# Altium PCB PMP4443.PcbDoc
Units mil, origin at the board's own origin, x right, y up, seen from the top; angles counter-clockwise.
Board outline 2136.81 x 1725.39 mil, 2 copper layers (Top Layer, Bottom Layer), stack 62 mil thick; 21 components, 12 nets, 49 pads, 3 vias.
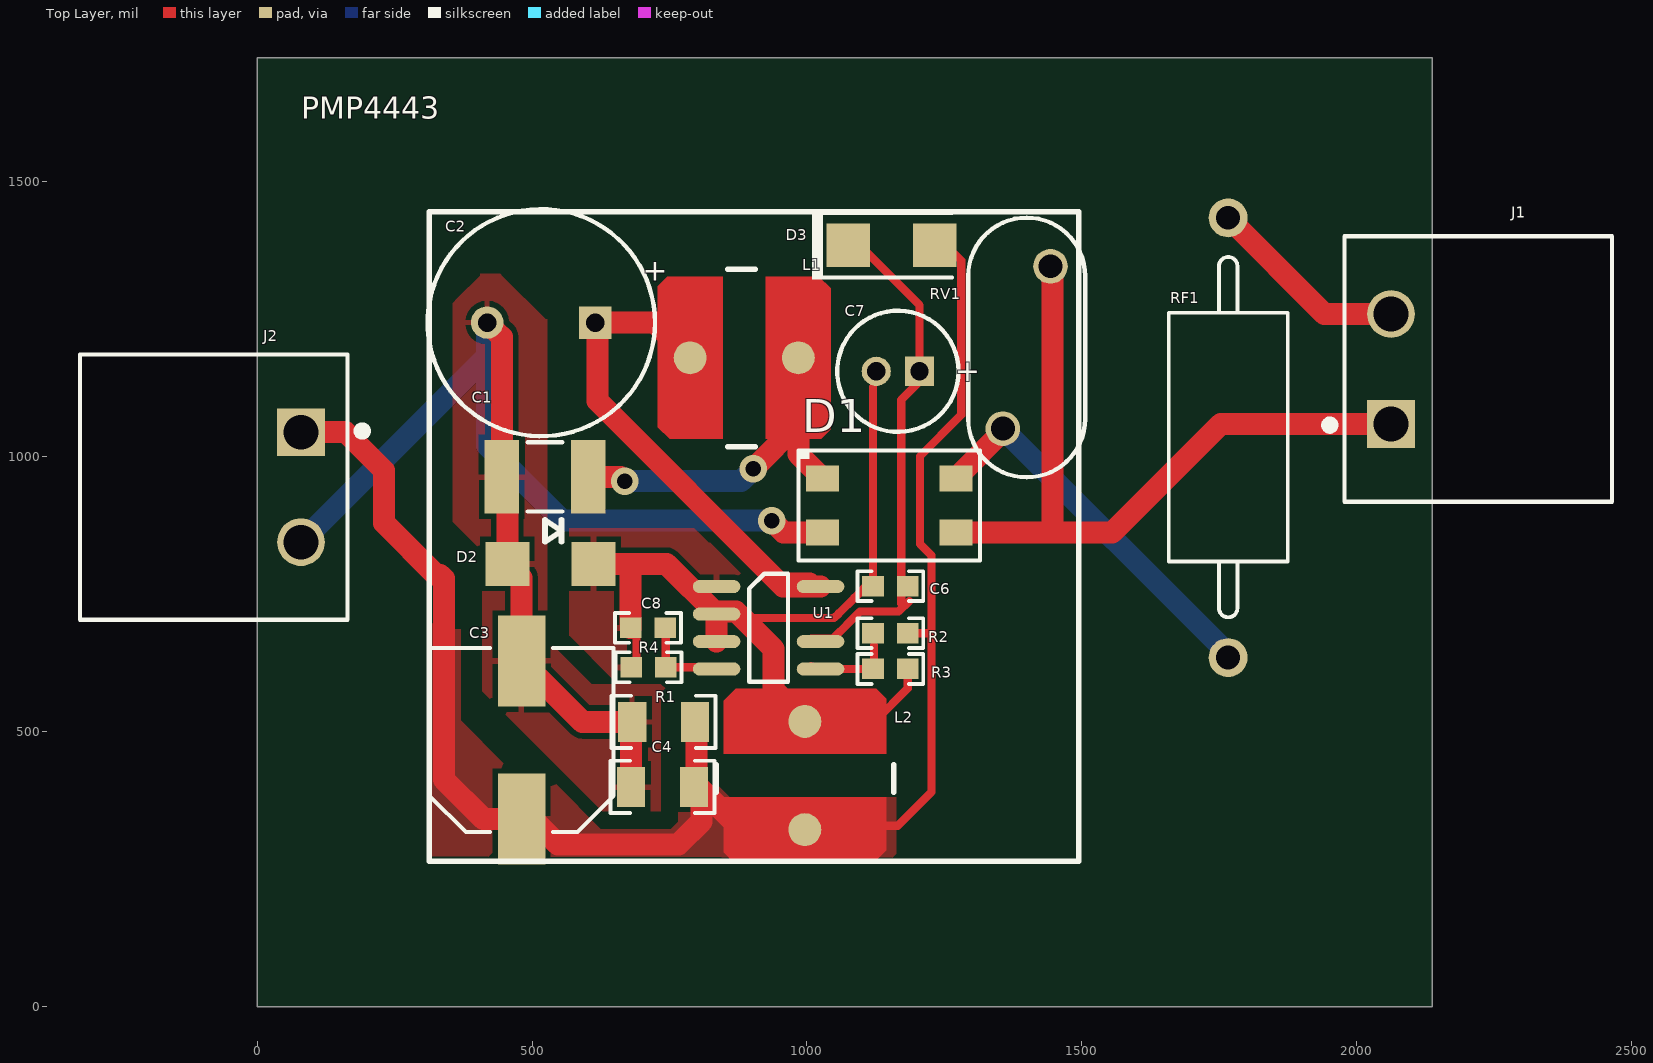
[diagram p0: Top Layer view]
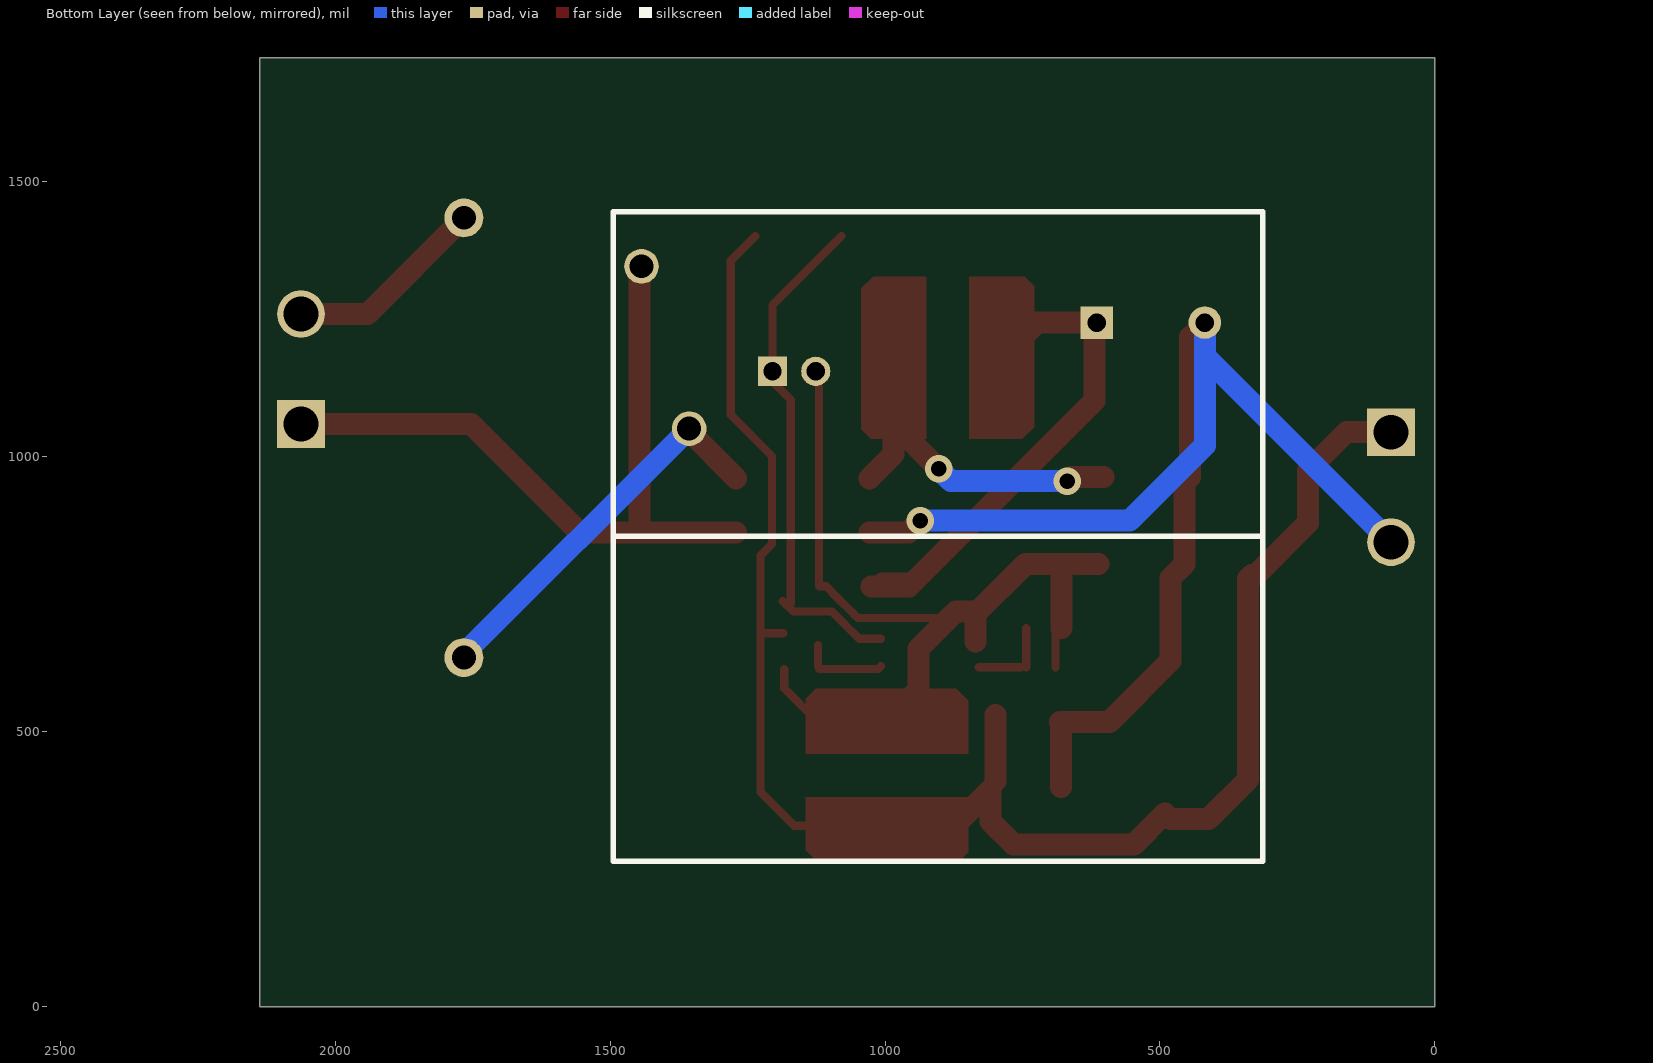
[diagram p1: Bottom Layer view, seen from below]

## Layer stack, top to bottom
Top Layer: signal copper 1.4
Dielectric: core 59.2, FR-4, Dk 4.8
Bottom Layer: signal copper 1.4

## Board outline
0,0 0,1725.39 2136.81,1725.39 2136.81,0

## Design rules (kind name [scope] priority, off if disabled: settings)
AcuteAngle [All] p1: minimum=4.50000000000000E+0001 checktracksonly=FALSE
AssemblyTestPointUsage [All] p1: valid=2
Clearance Clearance_1 [All] p1: gap=10
Clearance Clearance_BoardEdge_MountingHoles [OnCopper and InComponentClass('Mounting Holes') vs IsKeepOut] p2: gap=40
Clearance Clearance_BoardEdge_Poly [OnCopper and InPoly vs IsKeepOut] p3: gap=25
Clearance Clearance_BoardEdge [OnCopper and Not InComponentClass('Logo') and not InComponentClass('FiducialMark') and not InRegion(1000,500,4000,800) and Not IsKeepout vs IsKeepOut] p4: gap=75
Clearance Clearance_Poly [InPolygon] p5: gap=25
Clearance [All] p6: gap=7.87
ComponentClearance ComponentClearance_MountingHoles_FiducialMarks [InComponentClass('Mounting Holes') vs InComponentClass('FiducialMark')] p1: gap=0 collisioncheckmode=3 verticalgap=10 showdistances=FALSE
ComponentClearance ComponentClearance_Logo [InComponentClass('Logo')] p2: gap=0 collisioncheckmode=3 verticalgap=10 showdistances=FALSE
ComponentClearance ComponentClearance_ScrewToNut [(HasFootprint('NY PMS 440 0025 PH')) vs (HasFootprint('Keystone_1902C'))] p3: gap=0 collisioncheckmode=3 verticalgap=10 showdistances=FALSE
ComponentClearance ComponentClearance_MountingHoles [InComponentClass('Mounting Holes')] p4: gap=0 collisioncheckmode=3 verticalgap=100000 showdistances=FALSE
ComponentClearance ComponentClearance_SmallPassives [HasFootprint('0201*') or HasFootprint('0402*') or HasFootprint('0508') or HasFootprint('0603*') or HasFootprint('0612') or HasFootprint('0805*') or HasFootprint('0815*') or HasFootprint('0830*') or HasFootprint('1206*') or HasFootprint('1210*') or HasFootprint('1808*') or HasFootprint('1812*') or HasFootprint('1825*') or HasFootprint('2010*') or HasFootprint('2220*') or HasFootprint('2225*') or HasFootprint('2512*') or HasFootprint('2728*') or HasFootprint('3518*') vs HasFootprint('0201*') or HasFootprint('0402*') or HasFootprint('0508') or HasFootprint('0603*') or HasFootprint('0612') or HasFootprint('0805*') or HasFootprint('0815*') or HasFootprint('0830*') or HasFootprint('1206*') or HasFootprint('1210*') or HasFootprint('1808*') or HasFootprint('1812*') or HasFootprint('1825*') or HasFootprint('2010*') or HasFootprint('2220*') or HasFootprint('2225*') or HasFootprint('2512*') or HasFootprint('2728*') or HasFootprint('3518*')] p5: gap=0 collisioncheckmode=3 verticalgap=10 showdistances=FALSE
ComponentClearance ComponentClearance_THtoSMT [IsThruComponent vs IsSMTComponent] p6: gap=0 collisioncheckmode=3 verticalgap=30 showdistances=FALSE
ComponentClearance ComponentClearance_THtoTH [IsThruComponent vs IsThruComponent] p7: gap=0 collisioncheckmode=3 verticalgap=30 showdistances=FALSE
ComponentClearance [All] p8: gap=0 collisioncheckmode=3 verticalgap=10 showdistances=FALSE
ComponentClearance ComponentClearance_Shunt [InComponentClass('Header') vs InComponentClass('Shunt')] p9: gap=0 collisioncheckmode=3 verticalgap=0 showdistances=FALSE
DiffPairsRouting [All] p1: maxlimit=100 minlimit=10 mostfreqgap=10 maxuncoupledlength=1000
FabricationTestPointUsage TestPointUsage [All] p1: valid=2 allowmultiple=FALSE
FabricationTestpoint Testpoint [All] p1: side=3 testpointundercomponent=TRUE minsize=40 maxsize=100 preferedsize=60 minholesize=0 maxholesize=40 preferedholesize=32 testpointgrid=1 allowsidetop=TRUE allowsidebottom=TRUE usegrid=TRUE gridtolerance=0.01
FanoutControl Fanout_LCC [IsLCC] p1: bgadir=Out bgaviamode=Centered fanoutstyle=Auto fanoutdirection=Alternating viagrid=1 // Fanout_LCC (Default Rule)
FanoutControl Fanout_BGA [IsBGA] p2: bgadir=Out bgaviamode=Centered fanoutstyle=Auto fanoutdirection=Alternating viagrid=1 // Fanout_BGA (Default Rule)
FanoutControl Fanout_Default [All] p4: bgadir=Out bgaviamode=Centered fanoutstyle=Auto fanoutdirection=Alternating viagrid=1 // Fanout_Default (Default Rule)
FanoutControl Fanout_Small [(CompPinCount < 5)] p5: bgadir=Out bgaviamode=Centered fanoutstyle=Auto fanoutdirection=OutThenIn viagrid=1 // Fanout_Small (Default Rule)
HoleSize [All] p1: absolutevalues=TRUE maxlimit=251 minlimit=8 maxpercent=80.000 minpercent=20.000
MinimumAnnularRing MinimumAnnularRing_ThermalPadVias [IsVia and InAnyComponent] p1: minimumring=5.91
MinimumAnnularRing [All] p2: minimumring=9
MinimumSolderMaskSliver MinimumSolderMaskSliver_Logo [InComponentClass('Logo') vs InComponentClass('Logo')] p1: minsoldermaskwidth=0.7
MinimumSolderMaskSliver [All] p2: minsoldermaskwidth=3.94
PlaneConnect [All] p1: planeconnectstyle=Relief reliefexpansion=10 reliefentries=4 reliefconductorwidth=10 reliefairgap=10
PolygonConnect [All] p1: connectstyle=Relief reliefconductorwidth=10 reliefentries=4 polygonreliefangle="90 Angle" airgapwidth=10
RoomDefinition "V3-PMP4443-layout-Buck converter with  20Vout 2W" [InComponentClass('V3-PMP4443-layout-Buck converter with  20Vout 2W')] p1: confinementstyle=ConfineIn formatcopy=TRUE lockcomponents=FALSE outline -1076.06,-1819.28 923.94,-1819.28 923.94,-819.28 -1076.06,-819.28
RoutingVias ThermalPadVias [IsVia and InAnyComponent] p1: holewidth=7.87 width=19.68 viastyle="Through Hole" minholewidth=7.87 minwidth=19.68 maxholewidth=12.99 maxwidth=23.62
RoutingVias [All] p2: holewidth=16 width=34 viastyle="Through Hole" minholewidth=7.87 minwidth=26 maxholewidth=40 maxwidth=65
SMDToCorner [All] p1: distance=30000
SilkToSilkClearance [All] p1: silktosilkclearance=5
SilkscreenOverComponentPads [All] p1: minsilkscreentomaskgap=5
SolderMaskExpansion [All] p1: expansion=1.97
Width [All] p1: maxlimit=100 minlimit=6 preferedwidth=19.68 checkconnectedcopper=TRUE
14 further rules are at their usual default settings.

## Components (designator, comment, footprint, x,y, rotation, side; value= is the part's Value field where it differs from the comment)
C1 "VJ1812Y104KXEAT5Z" 1812 523.62,963.58 r180 top
C2 "UVC2G100MPD" VR_1000x1250 516.73,1244.09 r180 top (schematic designator C10)
C3 "EMVA500ADA101MHA0G" CAPSMT_62_HA0 480.94,484.72 r90 top (schematic designator C13)
C4 "12065C104JAT2A" 1206 737.2,399.61 r180 top (schematic designator C12)
C6 "06033D104KAT2A" 0603 1151.57,764.74 r180 top (schematic designator C7)
C7 "EEU-FM1E470" FM_500x1100 1165.35,1155.51 r180 top (schematic designator C8)
C8 "06033C101KAT2A" 0603 710.63,688.98 r180 top
D1 "RH06-T" MiniDIP 1149.61,911.42 r0 top (schematic designator D0)
D2 "US1G-E3/5AT" DO-214AC 533.46,805.12 r180 top
D3 "MURA160T3G" SMA 1153.54,1384.84 r0 top
J1 "20020110-H021A01LF" FCI_20020110-H021A01LF 2220.94,1159.72 r90 top (schematic designator J3)
J2 "20020110-H021A01LF" FCI_20020110-H021A01LF -79.06,944.72 r270 top
L1 "1mH" WE-PD2-L 885.83,1180.12 r180 top
L2 "220uH" WE-PD2-L 996.06,420.28 r270 top
R1 "RC1206FR-0720KL" 1206 739.17,517.72 r0 top (schematic designator R7)
R2 "RT0603DRE07336KL" 0603 1151.57,679.11 r0 top (schematic designator R4)
R3 "RT0603DRE0784K5L" 0603 1151.57,614.17 r180 top (schematic designator R6)
R4 "CRCW06031K30FKEA" 0603 711.61,617.13 r0 top
RF1 "PWR4522AS8R20JA" RES_PWR4522 1765.94,1034.72 r90 top (schematic designator RF2)
RV1 "S10K275E2" VAR_S10K275E2 1399.61,1198.82 r270 top
U1 "UCC28910D" D0007A_N 930.12,688.98 r0 top (schematic designator U2)

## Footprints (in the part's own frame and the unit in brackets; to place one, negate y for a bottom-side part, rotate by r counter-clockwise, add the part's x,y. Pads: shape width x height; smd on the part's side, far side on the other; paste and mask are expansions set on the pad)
0603 [mm] "0603 from SM-752 data"
  rect 1x0.95 smd: 1(-0.8,0) 2(0.8,0)
  silkscreen extent -1.52,-0.69 1.52,0.69, body extent -0.87,-0.47 0.87,0.47, height 0.85
1206 [mm] "1206 from SM-752 data"
  rect 1.3x1.85 smd: 1(-1.45,0) 2(1.45,0)
  silkscreen extent -2.4,-1.21 2.4,1.21, body extent -1.7,-0.9 1.7,0.9, height 1.35
1812 [mm]
  rect 1.6x3.4 smd: 1(-2,0) 2(2,0)
  silkscreen extent -0.8,-1.6 0.8,1.6, body extent -2.4,-1.7 2.4,1.7, height 1.35
CAPSMT_62_HA0 [mm] "8 x 10mm:  Chemi-Con HA0"
  rect 4.2x2.2 smd: 1(-3.65,0) 2(3.65,0)
  silkscreen extent -4.25,-4.25 4.25,4.25, body extent -4.26,-4.26 4.26,4.26, height 10.5
D0007A_N [mm] "SOIC, 7-Leads, Body 4.9x3.9mm, Pitch 1.27mm, IPC Medium Density"
  oval 2.2x0.6 smd: 1(-2.4,1.905) 2(-2.4,0.635) 3(-2.4,-0.635) 4(-2.4,-1.905) 5(2.4,-1.905) 6(2.4,-0.635) 8(2.4,1.905)
  silkscreen extent -0.9,-2.5 0.9,2.5, body extent -3,-2.5 3,2.5, height 1.54
DO-214AC [mil]
  rect 80x80 smd: 1(-78.5,0) 2(78.5,0)
  silkscreen extent -20,-80 10,-40
FCI_20020110-H021A01LF [mm] "FCI"
  rect 2.2x2.2 hole 1.6 paste+0 mask+0.05: 1(-2.54,4.03)
  round 2.2 hole 1.6 paste+0 mask+0.05: 2(2.54,4.03)
  silkscreen extent -6.13,-6.18 6.13,7.06, body extent -6.08,-6 6.08,6, height 8.67
FM_500x1100 [mm] "PANASONIC"
  rect 1.35x1.35 hole 0.838: 1(-1,0)
  round 1.35 hole 0.838: 2(1,0)
  silkscreen extent -2.8,-2.8 2.8,2.8, body extent -2.73,-2.75 2.75,2.75, height 12.51
MiniDIP [mm] "Land pattern created based on STEP model."
  rect 1.52x1.2 smd: 1(-3.075,1.25) 2(-3.075,-1.25) 3(3.075,-1.25) 4(3.075,1.25)
  silkscreen extent -4.19,-2.54 4.19,2.54, body extent -3.5,-2.45 3.5,2.45, height 2.75
RES_PWR4522 [mm] "Bourns fusible resistor"
  round 1.8 hole 1.1: 1(-10.16,0) 2(10.16,0)
  silkscreen extent -8.3,-2.76 8.35,2.74, body extent -10.58,-2.74 10.58,2.74, height 5.49
SMA [mm] "Molded Diode, 2-Leads, Body 4.3x2.6mm, IPC Medium Density, based on OnSemi component dimensions and land pattern"
  rect 2x2 smd: 1(-2,0) 2(2,0)
  silkscreen extent -3.66,-1.57 2.79,1.57, body extent -2.6,-1.3 2.6,1.3, height 2.42
VAR_S10K275E2 [mm] "EPCOS"
  round 1.6 hole 1.1: 1(-3.75,1.1) 2(3.75,-1.1)
  silkscreen extent -6,-2.7 6,2.7, body extent -5.98,-2.7 5.98,2.7, height 14.99
VR_1000x1250 [mm] "Nichicon"
  rect 1.5x1.5 hole 0.85: 1(-2.5,0)
  round 1.5 hole 0.85: 2(2.5,0)
  silkscreen extent -5.25,-5.25 5.25,5.25, body extent -5.21,-5.24 5.24,5.24, height 14.01
WE-PD2-L [mil] "WE, Inductor"
  round 60 smd: 1(-98.43,0) 2(98.43,0)
  Top Layer region: 39.37,147.64 39.37,-147.64 139.76,-147.64 157.48,-129.92 157.48,125.98 135.83,147.64
  Top Layer region: -39.37,-147.64 -39.37,147.64 -139.76,147.64 -157.48,129.92 -157.48,-125.98 -135.83,-147.64
  silkscreen extent -20,-161 30,161, body extent -157,-144 159,144, height 217

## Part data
C1: "CAP, CERM, 0.1uF, 500V, +/-10%, X7R, 1812"
C2: library part UVC2G8R2MPD, "CAP, AL, 10uF, 400V, +/-20%, TH"
C3: "CAP, AL, 100uF, 50V, +/-20%,  ohm, SMD"
C4: "CAP, CERM, 0.1uF, 50V, +/-5%, X7R, 1206"
C6: "CAP, CERM, 0.1uF, 25V, +/-10%, X5R, 0603"
C7: "CAP, AL, 47uF, 25V, +/-20%, 0.3 ohm, TH"
C8: "CAP, CERM, 100pF, 25V, +/-10%, X7R, 0603"
D1: "Diode, Switching-Bridge, 600V, 0.5A, MiniDIP"
D2: library part D_SCHOT_SS_SERIES, "Diode, Schottky, xxV, 1A"
D3: "Diode, Ultrafast, 600V, 1A, SMA"
J1 J2: "Terminal Block, 2x1, 5.08mm, TH"
L1: library part 76877530, "Inductor, Unshielded Drum Core, Metal Composite, 1mH, 0.3A, 2.78 ohm, SMD"
L2: library part 744775247, "Inductor, Unshielded Drum Core, Metal Composite, 470uH, 0.36A, 1.37 ohm, SMD"
R1: "RES, 20.0k ohm, 1%, 0.25W, 1206"
R2: "RES, 336k ohm, 0.5%, 0.1W, 0603"
R3: "RES, 84.5k ohm, 0.5%, 0.1W, 0603"
R4: "RES, 1.30k ohm, 1%, 0.1W, 0603"
RF1: "RES, 8.2 ohm, 5%, 3W, Fusible, TH"
RV1: "Varistor 275V RMS 10MM Radial, TH"
U1: "LOW STAND-BY POWER, CV / CC PWM HV SWITCHER WITH PRIMARY SIDE REGULATION, D0007A"

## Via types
v1: diameter 50, hole 28, Top Layer to Bottom Layer, 3 vias

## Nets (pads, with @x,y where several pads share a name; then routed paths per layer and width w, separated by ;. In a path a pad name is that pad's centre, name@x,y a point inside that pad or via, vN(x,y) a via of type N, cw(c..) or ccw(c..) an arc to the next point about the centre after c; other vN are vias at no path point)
GND0: C1.2 C2.2 C3.2 C4.2 D1.2 D2.2 J2.2 R1.1 | length 2383.1
  Top Layer w40: C2.2 444.88,1217.52 C1.2 454.96,953.5 D2.2 480.94,779.14 C3.2 591.65,517.72 R1.1 ; C4.2 R1.1@680.12,515.75 ; v1(936.02,883.86) 957.68,862.2 D1.2
  Bottom Layer w40: J2.2 418.31,1183.43 ; C2.2 418.31,1183.43 ; v1(936.02,883.86) 555.12,883.86 418.31,1020.67 418.31,1183.43
NetC1_1: C1.1 D1.1 L1.1 | length 666.2
  Top Layer w40: C1.1 660.43,963.58 v1(668.31,955.71) ; v1(902.56,978.35) 984.25,1060.04 ; L1.1 984.25,1060.04 ; D1.1 984.25,1004.92 984.25,1060.04
  Bottom Layer w40: v1(668.31,955.71) 879.92,955.71 v1(902.56,978.35)
NetC2_1: C2.1 L1.2 U1.8 | length 942.4
  Top Layer w40: L1.2 723.43,1244.09 C2.1 619.37,1239.88 619.37,1101.3 950.69,769.98 ; U1.8@1004.82,769.98 950.69,769.98 ; U1.8 956.69,763.98 950.69,769.98
NetC3_1: C3.1 C4.1 D3.2 J2.1 L2.2 R1.2 R2.2 | length 3086.2
  Top Layer w15: L2.2 1016.5,321.85 1023.39,328.74 1164.96,328.74 1226.38,390.16 1226.38,679.13 ; R2.2@1185.04,679.13 1226.38,679.13 ; D3.2@1235.98,1401.57 1280.51,1357.04 1280.51,1075.79 1205.71,1000.98 1205.71,841.54 1226.38,820.87 1226.38,679.13
  Top Layer w40: J2.1 160.94,1044.72 230.94,974.72 230.94,879.46 325.36,785.04 332.87,785.04 339.57,778.35 339.57,413.19 411.73,341.02 C3.1 ; C3.1@490.94,351.02 547.24,294.72 765.94,294.72 808.03,336.81 808.03,394.65 881.38,321.3 995.51,321.3 L2.2 ; C4.1@799.33,409.96 R1.2@799.33,529.96
NetC6_1: C6.1 C7.1 D3.1 U1.6 | length 941.3
  Top Layer w15: U1.6@1007.87,668.9 1046.73,668.9 1059.52,681.69 1082.89,705.02 ; D3.1@1078.98,1401.57 1204.72,1275.83 C7.1 1204.72,1136.81 1171.26,1103.35 1171.26,733.01 ; 1082.89,705.06 1096.33,718.5 1166.6,718.5 1186.02,737.93
NetC6_2: C6.2 C7.2 C8.2 D2.1 L2.1 R3.1 R4.1 U1.1 U1.2 U1.3 | length 1799.9
  Top Layer w15: R4.1@689.96,617.13 C8.2@689.96,702.01 ; 882.87,706.69 1049.21,706.69 1057.89,715.37 ; 973.43,546.26 998.03,521.65 1125.98,521.65 1183.07,578.74 R3.1 ; L2.1 L2.1@1014.76,537.4 ; 1057.89,715.42 1085.98,743.5 ; 1086.02,743.5 1107.26,764.74 C6.2 1120.08,1126.85
  Top Layer w40: C8.2 679.13,804.13 678.15,805.12 D2.1 744.49,805.12 U1.2 ; U1.3 U1.2 ; L2.1 938.98,575.79 938.98,650.59 882.87,706.69 870.67,718.9 835.63,718.9 U1.2
NetC8_1: C8.1 R4.2 U1.4 | length 147.8
  Top Layer w15: R4.2 C8.1@743.11,687.99 ; R4.2@752.95,617.13 U1.4@829.92,617.13
NetD0_3: D1.3 J1.1 RV1.1 | length 1359.3
  Top Layer w40: D1.3 1446.85,862.2 ; RV1.1 1446.85,1342.52 1446.85,862.2 ; J1.1 1752.64,1059.72 1555.12,862.2 1446.85,862.2
NetD0_4: D1.4 RF1.1 RV1.2 | length 712.2
  Top Layer w40: D1.4 1356.3,1046.26 RV1.2
  Bottom Layer w40: RV1.2 1765.94,641.54 RF1.1
NetD1_2: 
NetJ1_2: J1.2 RF1.2 | length 368.8
  Top Layer w40: RF1.2 1940.94,1259.72 J1.2
NetR2_1: R2.1 R3.2 U1.5 | length 151.8
  Top Layer w15: U1.5@1007.87,618.9 1012.6,614.17 R3.2 ; R3.2@1122.05,619.88 1122.05,657.48

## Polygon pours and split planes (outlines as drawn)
GND0 on Top Layer "Top Layer-No Net 4" (solid, pour order 19): 734.25,355.32 734.25,570.87 742.13,578.74 734.25,586.61 617.13,586.61 608.27,586.61 527.56,667.32 527.56,1250 524.61,1250 446.85,1327.76 441.93,1332.68 405.51,1332.68 405.51,1329.72 364.17,1288.39 355.32,1279.53 355.32,932.09 355.32,881.92 402.17,835.06 409.45,827.79 409.45,590.55 409.45,573.82 627.95,355.32
NetC6_2 on Top Layer "Top Layer-No Net 2" (solid, pour order 17): 660.43,560.04 660.43,581.69 569.88,672.24 567.91,674.21 567.91,870.08 795.28,870.08 876.97,788.39 962.6,702.76 962.6,566.93 912.4,566.93 900.59,578.74 898.62,580.71 898.62,648.62 812.01,648.62 799.21,661.42 795.28,665.35 795.28,709.65 795.28,716.54 774.61,737.2 771.65,734.25 691.93,734.25 691.93,561.02 688.98,558.07
NetC6_2 on Top Layer "Top Layer-No Net 3" (solid, remove dead copper, pour order 15): 568.9,845.47 568.9,683.98 568.9,679.13 639.76,608.27 641.73,606.3 698.82,606.3 698.82,723.43 709.65,712.6 799.21,712.6 799.21,653.54 809.06,643.7 925.2,643.7 925.2,728.35 932.09,735.24 823.82,843.5 568.9,843.5
NetC3_1 on Top Layer "Top Layer-No Net 1" (solid, remove dead copper, pour order 10): 1162.4,270.67 1162.4,379.17 1163.58,380.35 862.99,380.35 859.8,380.35 814.96,425.2 813.98,424.21 765.75,424.21 765.75,336.61 751.97,322.83 642.72,322.83 625,322.83 524.61,423.23 520.67,427.17 463.58,427.17 371.06,519.68 370.08,520.67 370.08,686.02 339.96,686.02 316.64,709.35 316.64,273.07

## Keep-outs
Keep-Out Layer:
  lines w10: 4565.94,-290.28 ccw(c4565.94,-285.28) 4570.95,-285.28 ; 4565.94,-290.28 ccw(c4565.94,-285.28) 4570.95,-285.28 ; 4565.94,-290.28 ccw(c4565.94,-285.28) 4570.95,-285.28 ; 4565.94,-290.28 ccw(c4565.94,-285.28) 4570.95,-285.28 ; 4565.94,-290.28 ccw(c4565.94,-285.28) 4570.95,-285.28 ; 4565.94,-290.28 ccw(c4565.94,-285.28) 4570.95,-285.28 ; 4565.94,3169.73 cw(c4565.94,3164.72) 4570.95,3164.72 ; 4565.94,3169.73 cw(c4565.94,3164.72) 4570.95,3164.72 ; 4565.94,3169.73 cw(c4565.94,3164.72) 4570.95,3164.72 ; 4565.94,3169.73 cw(c4565.94,3164.72) 4570.95,3164.72 ; 4565.94,3169.73 cw(c4565.94,3164.72) 4570.95,3164.72 ; 4565.94,3169.73 cw(c4565.94,3164.72) 4570.95,3164.72
  text ".Layer_Name" at 192.94,-1143.77 h60

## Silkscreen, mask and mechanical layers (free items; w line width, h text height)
Top Overlay:
  lines w10: 313.35,264.76 313.35,1445.87 1494.45,1445.87 1494.45,1052.68 1494.45,264.76 313.35,264.76
  text "PMP4443" at 79.72,1615.16 h40
Bottom Overlay:
  lines w10: 313.35,855.24 1494.45,855.24 ; 313.35,264.72 313.35,1445.63 1494.45,1445.63 1494.45,264.72 313.35,264.72
Drill Guide:
  text ".Layer_Name" at 192.94,-1143.77 h60
M1 Board Outline:
  lines w10: 0,0 2136.81,0 2136.81,1725.39 0,1725.39 0,0
  lines w47.24: 0,0 0,1725.39 2136.81,1725.39 2136.81,0 0,0
  text ".Layer_Name" at 192.94,-1143.77 h60
M2 Board Dimensions:
  text ".Layer_Name" at 192.94,-1143.77 h60
M3 3D STEP Top:
  text ".Layer_Name" at 192.94,-1143.77 h60
M4 3D STEP Bottom:
  text ".Layer_Name" at 192.94,-1143.77 h60
M5 Assembly Top:
  lines w10: -676.06,-1215.44 5923.94,-1215.44 ; -676.06,-1012.11 5925.94,-1012.11 ; -676.06,-808.78 -676.06,-1418.78 3328.94,-1418.78 5925.94,-1418.78 5925.94,-808.78 -675.56,-808.78 -675.56,-1418.78 899.94,-1418.78 ; 1788.94,-1418.78 1788.94,-808.78 ; 3055.94,-1012.11 3055.94,-808.78 ; 3895.94,-1012.11 3895.94,-808.78 ; 4517.94,-1425.28 4517.94,-1222.44
  text "COMPONENTS MARKED 'DNP' SHOULD NOT BE POPULATED." at 769.44,-603.78 h60
  text "ASSEMBLY VARIANT:" at 768.94,-719.28 h60
  text ".VariantName" at 1804.94,-719.28 h60
  text "PCB VIEWED FROM TOP SIDE" at -612.56,-940.94 h60
  text "BOARD #:" at 1863.94,-940.94 h60
  text ".PRJ_Number" at 2409.44,-940.94 h60
  text "REV:" at 3253.94,-940.94 h60
  text ".PCB_Rev" at 3545.44,-940.94 h60
  text "SVN REV:" at 4091.94,-940.94 h60
  text ".VersionControl_RevNumber" at 4597.94,-940.94 h60
  text "IGNORE ->" at -612.56,-1143.77 h60
  text "PLOT NAME =" at -612.56,-1349.61 h60
  text ".plot_File_Name" at 192.94,-1349.61 h60
  text "GENERATED    :" at 1865.94,-1349.61 h60
  text ".Print_Date" at 2735.44,-1349.61 h60
  text ".Print_Time" at 3464.44,-1349.61 h60
  text "TEXAS INSTRUMENTS" at 4728.94,-1349.61 h60
M6 Assembly Bottom:
  lines w10: -676.56,-1012.61 5925.44,-1012.61 ; -674.56,-1215.94 5925.44,-1215.94 ; 731.44,-1425.78 731.44,-1222.94 ; 1353.44,-1012.61 1353.44,-809.28 ; 2193.44,-1012.61 2193.44,-809.28 ; 3460.44,-1419.28 3460.44,-809.28 ; 4349.44,-1419.28 5924.94,-1419.28 5924.94,-809.28 -676.56,-809.28 -676.56,-1419.28 1920.44,-1419.28 5925.44,-1419.28 5925.44,-809.28
  text "COMPONENTS MARKED 'DNP' SHOULD NOT BE POPULATED." at 5717.94,-603.28 h60
  text ".VariantName" at 4673.94,-719.28 h60
  text "ASSEMBLY VARIANT:" at 5712.94,-719.28 h60
  text ".VersionControl_RevNumber" at 651.44,-941.44 h60
  text "SVN REV:" at 1157.44,-941.44 h60
  text ".PCB_Rev" at 1703.94,-941.44 h60
  text "REV:" at 1995.44,-941.44 h60
  text ".PRJ_Number" at 2839.94,-941.44 h60
  text "BOARD #:" at 3385.44,-941.44 h60
  text "PCB VIEWED FROM BOTTOM SIDE" at 5861.94,-941.44 h60
  text "IGNORE ->" at 2163.8,-1143.77 h60
  text "TEXAS INSTRUMENTS" at 520.44,-1350.11 h60
  text ".Print_Time" at 1784.94,-1350.11 h60
  text ".Print_Date" at 2513.94,-1350.11 h60
  text "GENERATED    :" at 3383.44,-1350.11 h60
  text ".plot_File_Name" at 5056.44,-1350.11 h60
  text "PLOT NAME =" at 5861.94,-1350.11 h60
M9 Title Sheet:
  drawing of 57 lines, arcs and shapes, not listed
  text "1" at 355.78,7751.22 h70
  text "2" at 2851.44,7751.22 h70
  text "3" at 5340.79,7751.22 h70
  text "4" at 7847.46,7751.22 h70
  text "5" at 10346.44,7751.22 h70
  text "6" at 12851.44,7751.22 h70
  text "A" at -800.56,6608.22 h70
  text "A" at 13999.44,6608.22 h70
  text "B" at -800.56,4228.22 h70
  text "B" at 13999.44,4228.22 h70
  text "C" at -800.56,1853.22 h70
  text "C" at 13999.44,1853.22 h70
  text "PROJECT TITLE:" at 10959.44,-7.78 h45
  text ".PRJ_Title" at 11009.44,-141.1 h70
  text "DESIGNED FOR:" at 10959.44,-308.78 h45
  text ".PRJ_Customer" at 11009.44,-448.78 h70
  text "D" at -800.56,-516.78 h70
  text "D" at 13999.44,-516.78 h70
  text "FILE NAME:" at 10959.44,-608.78 h45
  text ".PCB_File_Name_No_Path" at 11009.44,-728.78 h70
  text "Texas Instruments (TI) and/or its licensors do not warrant the accuracy or completeness of this specification" at 5989.94,-890.61 h45
  text "ENGINEER:" at 10959.44,-898.78 h45
  text "LAYOUT BY:" at 12464.44,-898.78 h45
  text "or any information contained therein. TI and/or its licensors do not warrant that this design will meet" at 5944.96,-1003.28 h45
  text ".PRJ_Engineer" at 11009.44,-1053.77 h70
  text ".PCB_Layout" at 12514.94,-1053.77 h70
  text "the specifications, will be suitable for your application or fit for any particular purpose, or will operate in" at 5944.96,-1115.94 h45
  text ".Layer_Name" at 192.94,-1143.77 h60
  text "ALTIUM DESIGNER VERSION:" at 12464.44,-1208.78 h45
  text "an implementation. TI and/or its licensors do not warrant that the design is production worthy. You should" at 5944.96,-1228.61 h45
  text "completely validate and test your design implementation to confirm the system functionality for your application." at 5989.94,-1341.28 h45
  text ".print_Scale" at 11009.44,-1342.1 h70
  text ".Application_BuildNumber" at 12514.94,-1342.1 h70
  text "1" at 355.78,-1548.78 h70
  text "2" at 2851.44,-1548.78 h70
  text "3" at 5340.79,-1548.78 h70
  text "4" at 7847.46,-1548.78 h70
  text "5" at 10346.44,-1548.78 h70
  text "6" at 12851.44,-1548.78 h70
M10 Fab Notes:
  drawing of 185 lines, arcs and shapes, not listed
  text "DESIGN INFORMATION" at 11996.96,5624.72 h60
  text "MIN. TRACK WIDTH:" at 11352.4,5444.72 h60
  text "15" at 12448.65,5444.73 h60
  text "MIL" at 12603.4,5444.72 h60
  text "MIN. CLEARANCE:" at 11352.4,5312.72 h60
  text "0.2" at 12388.65,5312.73 h60
  text "mm" at 12603.4,5312.72 h60
  text "MIN. VIA PAD SIZE:" at 11352.4,5180.72 h60
  text "20" at 12418.66,5180.73 h60
  text "MIL" at 12603.4,5180.72 h60
  text "0.05mm (2MIL)" at 12047.4,5039.01 h60
  text "MINIMUM ANNULAR RING" at 11023.17,5034.73 h60
  text "EXTERNAL" at 12755.4,5034.73 h60
  text "PER" at 11223.17,4916.73 h60
  text "IPC-D-275 CLASS 2 LEVEL C" at 11443.17,4916.72 h60
  text "MIL, HOLES" at 12931.4,4804.44 h60
  text "+/-" at 12538.94,4803.73 h60
  text "+/-" at 13392.94,4803.73 h60
  text "REGISTRATION TOLERANCES:" at 11023.17,4798.72 h60
  text "METAL" at 12222.94,4798.72 h60
  text "5" at 12799.15,4798.73 h60
  text "3" at 13632.15,4798.73 h60
  text "MIL" at 13748.4,4798.72 h60
  text "MATERIAL:" at 10948.4,4589.27 h60
  text "FR-4 High Tg" at 11934.85,4448.93 h60
  text "FR-408" at 11369.41,4440.36 h60
  text "X" at 11781.4,4440.36 h60
  text "OTHER" at 12857.4,4440.36 h60
  text "62 MIL (1.6mm) +/-10%" at 11689.51,4277.65 h60
  text "THICKNESS:" at 11023.17,4273.36 h60
  text "X" at 11561.34,4273.36 h60
  text "OTHER" at 12974.4,4273.36 h60
  text "TOLERANCE:" at 11023.17,4115.36 h60
  text "X" at 11862.48,4115.36 h60
  text "ANSI IPC-6012 TYPE 3 CLASS 2" at 12049.42,4115.36 h60
  text "OTHER +/-" at 12049.4,3959.36 h60
  text "BOW & TWIST:" at 11023.17,3802.36 h60
  text "X" at 11862.48,3802.36 h60
  text "ANSI IPC-6012 TYPE 3 CLASS 2" at 12049.42,3802.36 h60
  text "OTHER +/-" at 12049.4,3643.86 h60
  text "DRILLING:" at 10948.4,3505.36 h60
  text "REFERENCE:" at 11023.17,3388.36 h60
  text "X" at 11671.4,3388.36 h60
  text "AS SHOWN" at 11858.4,3388.36 h60
  text "X" at 12572.4,3388.36 h60
  text "NC_DRILL FILES" at 12709.4,3388.36 h60
  text "PTH MIN COPPER THICKNESS:" at 11023.17,3230.36 h60
  text "X" at 12373.4,3230.36 h60
  text "1MIL" at 12510.4,3230.36 h60
  text "OTHER" at 13007.4,3230.36 h60
  text "BOARD FINISH:" at 10948.4,3071.36 h60
  text "SILKSCREEN:" at 11103.63,2953.36 h60
  text "X" at 12052.4,2953.36 h60
  text "TOP" at 12178.4,2953.36 h60
  text "X" at 12562.4,2953.36 h60
  text "BOTTOM" at 12689.4,2953.36 h60
  text "SILKSCREEN COLOR:" at 11103.63,2786.36 h60
  text "X" at 12051.36,2786.36 h60
  text "WHITE" at 12178.4,2786.36 h60
  text "OTHER" at 12689.4,2786.36 h60
  text "SOLDER RESIST COLOR:" at 11103.63,2616.36 h60
  text "X" at 11671.37,2457.17 h60
  text "GREEN" at 11798.4,2457.17 h60
  text "BLUE" at 12389.4,2457.17 h60
  text "OTHER" at 12927.4,2457.17 h60
  text "IMMERSION GOLD (ENIG)" at 12009.4,2268.65 h60
  text "ENEPIG" at 13346.94,2265.36 h60
  text "SURFACE FINISH:" at 10948.4,2264.36 h60
  text "X" at 11822.46,2264.36 h60
  text "IMM. TIN/SILVER OR EQUIV" at 11277.94,2107.36 h60
  text "OTHER" at 12709.4,2107.36 h60
  text "ARRAY/PANEL:" at 10948.4,1928.36 h60
  text "CUT AND TRIM PER MECH LAYER 1" at 12009.41,1924.08 h60
  text "N.C. ROUTE" at 12009.4,1772.36 h60
  text "X" at 12688.4,1772.36 h60
  text "V. SCORE" at 12875.4,1772.36 h60
  text "CERTIFICATION:" at 10948.4,1635.36 h60
  text "MATERIALS AND WORKMANSHIP FOR ALL PCBS" at 11673.4,1635.36 h60
  text "TO MEET OR EXCEED THE REQUIREMENTS OF:" at 11673.4,1537.36 h60
  text "X" at 11299.91,1400.86 h60
  text "ANSI IPC-A-600F CLASS ->" at 11438.91,1400.86 h60
  text "X" at 13077.96,1400.86 h60
  text "2" at 13196.91,1400.86 h60
  text "1" at 12881.91,1399.36 h60
  text "3" at 13550.91,1399.36 h60
  text "X" at 11301.96,1241.36 h60
  text "UL 94V-0" at 11438.91,1241.36 h60
  text "X" at 12113.96,1241.36 h60
  text "RoHS" at 12250.91,1241.36 h60
  text "OTHER" at 12895.31,1241.36 h60
  text "PER ORDER" at 13292.37,1241.36 h60
  text "ADDITIONAL REQUIREMENTS:" at 10948.4,1100.36 h60
  text "MICROSECTION:" at 11023.17,985.36 h60
  text "YES" at 11928.91,985.36 h60
  text "REQUIRED" at 12790.4,829.22 h60
  text "BARE BOARD ELEC. TEST:" at 11023.17,826.36 h60
  text "NONE" at 12328.91,826.36 h60
  text "X" at 12663.4,826.36 h60
  text "PER ORDER" at 13382.4,826.36 h60
  text "MANUFACTURER'S UL:" at 11023.17,669.36 h60
  text "RAIL" at 12188.91,665.08 h60
  text "METAL" at 12680.72,665.08 h60
  text "X" at 13055.94,664.72 h60
  text "SILK" at 13192.4,665.08 h60
  text ".Layer_Name" at 192.94,-1143.77 h60
M11 Gerber Information:
  lines w10: -676.06,-1215.44 5923.94,-1215.44 ; -676.06,-1012.11 5925.94,-1012.11 ; -676.06,-808.78 -676.06,-1418.78 3328.94,-1418.78 5925.94,-1418.78 5925.94,-808.78 -675.56,-808.78 -675.56,-1418.78 899.94,-1418.78 ; 1788.94,-1418.78 1788.94,-808.78 ; 3055.94,-1012.11 3055.94,-808.78 ; 3895.94,-1012.11 3895.94,-808.78 ; 4517.94,-1425.28 4517.94,-1222.44
  text "ALL ARTWORK VIEWED FROM TOP SIDE" at -612.56,-940.94 h60
  text "BOARD #:" at 1863.94,-940.94 h60
  text ".PRJ_Number" at 2409.44,-940.94 h60
  text "REV:" at 3253.94,-940.94 h60
  text ".PCB_Rev" at 3545.44,-940.94 h60
  text "SVN REV:" at 4091.94,-940.94 h60
  text ".VersionControl_RevNumber" at 4597.94,-940.94 h60
  text "LAYER NAME =" at -612.56,-1143.77 h60
  text "PLOT NAME =" at -612.56,-1349.61 h60
  text ".plot_File_Name" at 192.94,-1349.61 h60
  text "GENERATED    :" at 1865.94,-1349.61 h60
  text ".Print_Date" at 2735.44,-1349.61 h60
  text ".Print_Time" at 3464.44,-1349.61 h60
  text "TEXAS INSTRUMENTS" at 4728.94,-1349.61 h60
M12 Stackup:
  lines w6: 10975.94,7174.72 13525.94,7174.72 ; 10975.94,7279.12 13525.94,7279.12 ; 10915.94,6689.72 ccw(c10949.94,6689.72) 10949.94,6655.72 13551.94,6655.72 ccw(c13551.94,6689.72) 13585.94,6689.72 13585.94,7395.72 ccw(c13551.94,7395.72) 13551.94,7429.72 10949.94,7429.72 ccw(c10949.94,7395.72) 10915.94,7395.72 10915.94,6689.72
  text "The Stackup Legend below this is static." at 11221.44,7589.22 h60
  text "If you change the stackup, update the Legend." at 11231.44,7499.22 h60
  text "Layer Stack Up Detail for: Ref_Design.PcbDoc" at 10975.94,7311.82 h57
  text "Layer" at 10975.94,7240.12 h24
  text "Gerber" at 11871.76,7240.12 h24
  text "Copper" at 12435.28,7240.12 h24
  text "Dielectric" at 13037.99,7240.12 h24
  text "Name" at 10975.94,7192.12 h24
  text "Document" at 11871.76,7192.12 h24
  text "Thickness" at 12435.28,7192.12 h24
  text "Material" at 13037.99,7192.12 h24
  text "Top Solder Mask" at 10975.94,7099.16 h34
  text "(.GTS)" at 11871.76,7099.16 h34
  text "Solder Resist" at 13037.99,7099.16 h34
  text "Top Layer" at 10975.94,7002.41 h34
  text "(.GTL)" at 11871.76,7002.41 h34
  text "1.4mil" at 12435.28,7002.41 h34
  text "FR-4" at 13037.99,6954.04 h34
  text "Bottom Layer" at 10975.94,6905.66 h34
  text "(.GBL)" at 11871.76,6905.66 h34
  text "1.4mil" at 12435.28,6905.66 h34
  text "Bottom Solder Mask" at 10975.94,6808.91 h34
  text "(.GBS)" at 11871.76,6808.91 h34
  text "Solder Resist" at 13037.99,6808.91 h34
  text ".Layer_Name" at 192.94,-1143.77 h60
M13 Component Bodies Top:
  text ".Layer_Name" at 192.94,-1143.77 h60
M14 Component Bodies Bottom:
  text ".Layer_Name" at 192.94,-1143.77 h60
M15 Courtyards Top:
  text ".Layer_Name" at 192.94,-1143.77 h60
M16 Courtyards Bottom:
  text ".Layer_Name" at 192.94,-1143.77 h60
Drill Drawing:
  text ".Layer_Name" at 192.94,-1143.77 h60

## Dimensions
0,0 to 0,1725.39 on M1 Board Outline
0,0 to 2136.81,0 on M1 Board Outline
1494.45,264.76 to 1230.32,394.09 on Top Overlay
1494.45,855.24 to 1494.45,1445.63 on Bottom Overlay
313.35,264.76 to 313.35,1445.87 on Top Overlay
313.35,1445.87 to 1494.45,264.76 on Top Overlay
